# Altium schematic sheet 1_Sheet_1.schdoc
size 302 x 215 mm; Name: A_A4; Symbol: A_A4; Device: A_A4; @Project Name: Sheet_1; REV: 1.0; Date: 2026-04-08; Sheet: 1/1; Draw By: nitishsharma; Company: Your Company; Convert to PCB: yes; Add into BOM: yes; spicePre: .
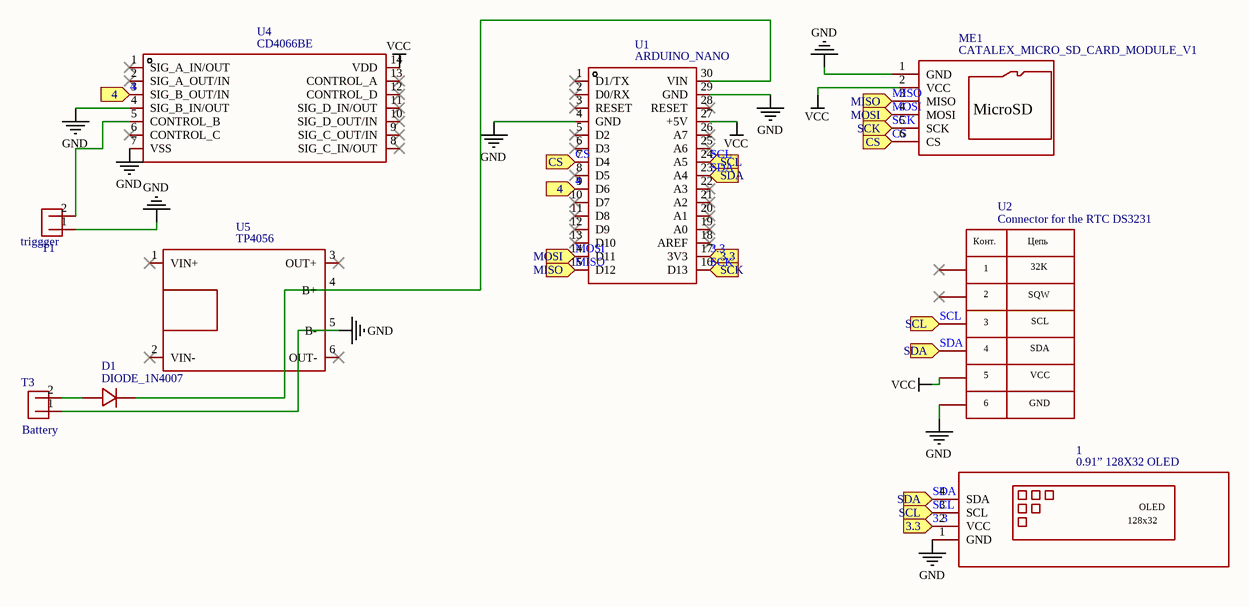
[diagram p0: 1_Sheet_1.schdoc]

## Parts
1  0.91” 128X32 OLED  [DISPLAY-OLED-128X32]
D1  DIODE_1N4007  [DIODE_1N4007]
ME1  CATALEX_MICRO_SD_CARD_MODULE_V1  [MICRO_SD_CARD_MODULE_V1]
T1  triggger  [M02 SCREW TERMINAL 5MM 10X8MM]
T3  Battery  [M02 SCREW TERMINAL 5MM 10X8MM]
U1  ARDUINO_NANO  [COMM-TH_ARDUINO_NANO]
U2  Connector for the RTC DS3231  [DS3231-RTC-MODULE]
U4  CD4066BE  [DIP-14_L19.2-W6.6-P2.54-LS10.9-BL]
U5  TP4056

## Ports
3.3 (in), 4 (in), CS (in), MISO (in), MOSI (in), SCK (in), SCL (in), SDA (in)

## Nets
GND: 1.1(GND) ME1.1(GND) T1.1 T3.1 U1.4(GND) U1.29(GND) U2.6(GND) U4.4(SIG_B_IN/OUT) U4.7(VSS) U5.5(B-)
VCC: ME1.2(VCC) U1.27(+5V) U2.5(VCC) U4.14(VDD)
3.3: 1.2(VCC) U1.17(3V3) ; port 3.3
4: U1.9(D6) U4.3(SIG_B_OUT/IN) ; port 4
CS: ME1.6(CS) U1.7(D4) ; port CS
MISO: ME1.3(MISO) U1.15(D12) ; port MISO
MOSI: ME1.4(MOSI) U1.14(D11) ; port MOSI
SCK: ME1.5(SCK) U1.16(D13) ; port SCK
SCL: 1.3(SCL) U1.24(A5) U2.3(SCL) ; port SCL
SDA: 1.4(SDA) U1.23(A4) U2.4(SDA) ; port SDA
NetD1_1: D1.1(A) T3.2
NetD1_2: D1.2(K) U1.30(VIN) U5.4(B+)
NetT1_2: T1.2 U4.5(CONTROL_B)

Not connected (* = marked no-connect by the designer): U1 1(D1/TX)* 2(D0/RX)* 3(RESET)* 5(D2)* 6(D3)* 8(D5)* 10(D7)* 11(D8)* 12(D9)* 13(D10)* 18(AREF)* 19(A0)* 20(A1)* 21(A2)* 22(A3)* 25(A6)* 26(A7)* 28(RESET)*; U2 1(32K)* 2(SQW)*; U4 1(SIG_A_IN/OUT)* 2(SIG_A_OUT/IN)* 6(CONTROL_C)* 8(SIG_C_IN/OUT)* 9(SIG_C_OUT/IN)* 10(SIG_D_OUT/IN)* 11(SIG_D_IN/OUT)* 12(CONTROL_D)* 13(CONTROL_A)*; U5 1(VIN+)* 2(VIN-)* 3(OUT+)* 6(OUT-)*

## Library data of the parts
1 = 0.91” 128X32 OLED: Convert to PCB: yes; Contributor: MAYURESH INAMDAR
D1 = DIODE_1N4007: Manufacturer: ST(先科); Manufacturer Part: 1N4007; Value: Diode; Convert to PCB: yes; Contributor: Darvin995
ME1 = CATALEX_MICRO_SD_CARD_MODULE_V1: Convert to PCB: yes; Contributor: crisav
T1 = triggger: Convert to PCB: yes; Contributor: serioga.com
T3 = Battery: Convert to PCB: yes; Contributor: serioga.com
U1 = ARDUINO_NANO: Manufacturer: null; Convert to PCB: yes; Contributor: lcsc
U2 = Connector for the RTC DS3231: Convert to PCB: yes; Contributor: k5283kc
U4 = CD4066BE: Manufacturer: TI(德州仪器); Convert to PCB: yes; sourceId: 8uoGAS9rJ
U5 = TP4056: Convert to PCB: yes; Origin Footprint: BATTERY-CHARGER-TP4056; Contributor: mario_ayala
